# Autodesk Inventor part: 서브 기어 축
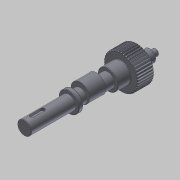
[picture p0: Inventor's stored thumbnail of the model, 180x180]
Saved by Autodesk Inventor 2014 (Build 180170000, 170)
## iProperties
Created: 2018-12
Part Number: 서브 기어 축
Material: 강철, 연강
Document SubType Name: Modeling
Designer: mduedu
Categories: <?xml version="1.0" encoding="UTF-16"?> <MemberInstance><Categories><FamilyTemplate><FamilyTemplateParameter ValueType="xs:double" Id="1" ObjectReferenceKey="da
Density: 7.86 g/cm^3
Appearance: Steel
Mass: 514.759 g
Surface Area: 160.366 cm^2
Volume: 65.491 cm^3
Author: mduedu
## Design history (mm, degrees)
sketch "Sketch1"
  geometry: C1 r 21.3 at (0, 0)
  constraints: 1 centre point
  dimensions: "d0" = 42.6 diameter of C1 (= da_da)
extrude "Extrusion1" new body sketch "Sketch1" distance "d1" = 20 (= da_b); taper "d2" = 0 deg
workplane "Work Plane2"
sketch "Sketch2"
  geometry: C1 r 21.3 at (0, 0) reference; C2 r 20.5 at (0, 0)
  constraints: 1 centre point, 1 coincident
  dimensions: "d3" = 41 diameter of C2 (= da_dw)
feature "피치 지름" sketch "Sketch2" dims "d4" = 10, "d5" = 0
workplane "Work Plane8"
workplane "Work Plane9"
chamfer "모따기1" distance "d49" = 1; stored, may be unused: second distance "d50" = 2, angle "d51" = 45 deg
sketch "스케치3"
  geometry: C1 r 12.5 at (0, 0); 1 further point
  constraints: 1 centre point, 1 coincident
  dimensions: "d52" = 25 diameter of C1
extrude "돌출2" join sketch "스케치3" distance "d53" = 16; taper "d54" = 0 deg
sketch "스케치4"
  geometry: C1 r 8.5 at (0, 0); 1 further point
  constraints: 1 centre point, 1 coincident
  dimensions: "d55" = 17 diameter of C1
extrude "돌출3" join sketch "스케치4" distance "d56" = 103; taper "d57" = 0 deg
sketch "스케치5"
  geometry: C1 r 7.5 at (0, 0); 1 further point
  constraints: 1 centre point, 1 coincident
  dimensions: "d58" = 15 diameter of C1
extrude "돌출4" join sketch "스케치5" distance "d59" = 16; taper "d60" = 0 deg
sketch "스케치6"
  geometry: C1 r 4 at (0, 0); 1 further point
  constraints: 1 centre point, 1 coincident
  dimensions: "d61" = 8 diameter of C1
extrude "돌출5" join sketch "스케치6" distance "d62" = 7; taper "d63" = 0 deg
chamfer "모따기2" distance "d64" = 0.5; stored, may be unused: second distance "d65" = 2, angle "d66" = 45 deg
fillet "모깎기1" dims "d67" = 0.5
feature "스퍼 기어" dims "da_b" = 20, "da_d" = 41, "da_aw" = 31, "da_da" = 42.6, "da_df" = 39.086, "da_dw" = 41, angle "da_beta" = 0 deg, "da_lefttooth" = 0, "da_righttooth" = 0
node "작업 평면11"
sketch "스케치7"
  geometry: C1 r 11.5 at (0, 3); C2 r 8.5 at (0, 0) reference; 1 further point
  constraints: 1 centre point, 1 tangent, 1 vertical alignment
  dimensions: "d69" = 3 distance of point (0, 0) C1.centre; "d70" = 23 diameter of C1 (derived)
extrude "돌출6" join sketch "스케치7" stored distance "d71" = 20; taper "d72" = 0 deg
node "작업 평면12"
sketch "스케치8"
  geometry: C1 r 12.5 at (0, 0) reference; C2 r 12.5 at (0, 0) reference; 1 further point
extrude "돌출7" join sketch "스케치8" distance "d74" = 5; taper "d75" = 0 deg
chamfer "모따기3" distance "d76" = 0.5; stored, may be unused: second distance "d77" = 2, angle "d78" = 45 deg
sketch "스케치9"
  geometry: L1 (-8, 139)-(8, 139) reference; L2 (0, 139)-(0, 0); L3 (-8.5, 84)-(-8.5, 138.5) reference; L4 (-8.5, 115)-(0, 115); L5 (-8.5, 115)-(-8.5, 113.5); L6 (-8.5, 113.5)-(-7, 115); L7 (-7, 115)-(-8.5, 115)
  constraints: 10 end point, 4 point on line, 2 perpendicular, 1 collinear, 1 midpoint
  dimensions: "d79" = 24 distance between parallel lines of L4 L1; "d80" = 3 diameter of L5.end L4; "d81" = 45 deg angle of L6 L3
revolve "회전1" sketch "스케치9" stored, may be unused: angle "d82" = 90 deg
sketch "스케치10"
  geometry: L1 (-8.5, 116.5)-(-7, 115) reference; L2 (-8.5, 113.5)-(-7, 115) reference; 2 further points
  constraints: 1 coincident
node "작업점1"
node "작업 평면13"
sketch "스케치11"
  geometry: L1 (-2.5, 93.5)-(-2.5, 80.5); L2 (2.5, 80.5)-(2.5, 93.5); L3 (-8, 103)-(8, 103) reference; A1 r 2.5 centre (0, 93.5) between (2.5, 93.5) and (-2.5, 93.5); A2 r 2.5 centre (0, 80.5) between (-2.5, 80.5) and (2.5, 80.5); 1 further point
  constraints: 4 end point, 4 point on circle, 4 tangent, 2 centre point, 2 vertical alignment, 1 parallel
  dimensions: "d83" = 7 distance edge to line of A1 L3; "d84" = 18 dimension on A2 A1; "d85" = 5 distance between parallel lines of L1 L2
extrude "돌출8" cut sketch "스케치11" distance "d86" = 3; taper "d87" = 0 deg
sketch "스케치12" dims "d88" = 32
  geometry: C1 r 0.5 at (0, -16); 2 further points
  constraints: 2 vertical alignment, 1 centre point, 1 coincident, 2 other
  dimensions: "d89" = 1 diameter of C1
extrude "돌출9" join sketch "스케치12" distance "d90" = 0.3; taper "d91" = 0 deg
sketch "스케치13"
  geometry: C1 r 11.5 at (0, 3) reference; 1 further point
  node "절단 모서리 투영1"
body "Solid1"
body "Srf1"
node "투영된 루프1"
other parameters: "d16" = 31 (= da_aw), "d17" = 0, "d34" = 0.76624 (computed from da_z), "d39" = 0, "d41" = 0, "d43" = 31 (= da_aw), "d46" = 31 (= da_aw), "d47" = 0, "d48" = 0, "d68" = 24, "d73" = 48
